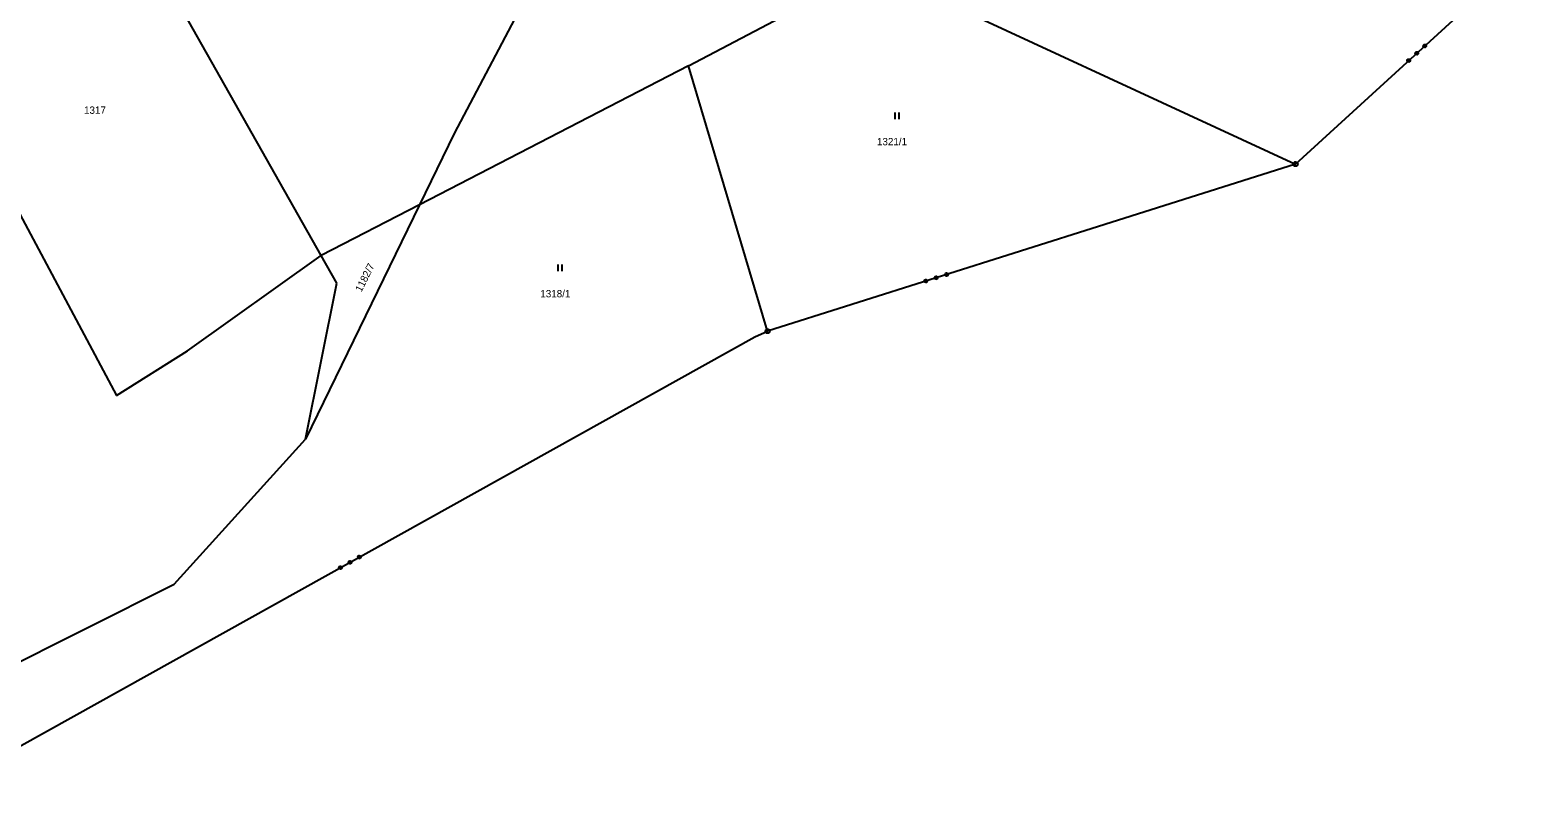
# Model space of a CAD drawing. Extents: x -747792 to -745414, y -1093712 to -1091463.
# Drawn here: x -746991.3 to -746816.9, y -1093671.2 to -1093583.6 of the extents above; entities that cross this region are included whole.
import ezdxf

# ---------------------------------------------------------------- set-up
doc = ezdxf.new("R2010")
doc.units = 0
for name, color, linetype in [('Pracovní_bod JDTM STC_VC', 7, 'Continuous'), ('Pracovní_bod JDTM STC_VC - číslo', 7, 'Continuous'), ('Pracovní_bod NN - výška', 7, 'Continuous'), ('Pracovní_bod VN - výška', 7, 'Continuous')]:
    doc.layers.add(name, color=color, linetype=linetype)

msp = doc.modelspace()

# ---------------------------------------------------------------- linework, layer by layer
at = {"layer": 'Pracovní_bod JDTM STC_VC - číslo'}
for points in [[(-746891.29, -1093593.11), (-746891.29, -1093593.86)], [(-746890.79, -1093593.86), (-746890.79, -1093593.11)], [(-746930.26, -1093610.7), (-746930.26, -1093611.45)], [(-746929.76, -1093611.45), (-746929.76, -1093610.7)]]:
    msp.add_lwpolyline(points, dxfattribs=at)
at = {"layer": 'Pracovní_bod NN - výška'}
for points in [[(-746957.63, -1093609.64), (-746987.25, -1093557.25)], [(-746925, -1093562.76), (-746942.26, -1093595.53)], [(-747010.59, -1093570.96), (-746981.31, -1093625.83)], [(-746844.91, -1093599.07), (-746816.88, -1093573.43)], [(-746915.14, -1093587.71), (-746893.79, -1093576.47)], [(-746893.79, -1093576.47), (-746844.91, -1093599.07)], [(-746830.95, -1093586.08), (-746830.82, -1093586.09), (-746830.73, -1093586.19), (-746830.73, -1093586.32), (-746830.83, -1093586.42), (-746830.97, -1093586.41), (-746831.06, -1093586.31), (-746831.05, -1093586.18), (-746830.95, -1093586.08), (-746830.94, -1093586.1), (-746831.03, -1093586.18), (-746831.03, -1093586.24), (-746830.89, -1093586.11), (-746830.83, -1093586.11), (-746831.04, -1093586.3), (-746831.01, -1093586.33), (-746830.8, -1093586.14), (-746830.77, -1093586.17), (-746830.98, -1093586.36), (-746830.95, -1093586.39), (-746830.75, -1093586.2), (-746830.75, -1093586.25), (-746830.9, -1093586.39), (-746830.84, -1093586.39), (-746830.75, -1093586.31)], [(-746830.03, -1093585.24), (-746829.89, -1093585.24), (-746829.8, -1093585.34), (-746829.81, -1093585.48), (-746829.91, -1093585.57), (-746830.04, -1093585.56), (-746830.13, -1093585.46), (-746830.12, -1093585.33), (-746830.03, -1093585.24), (-746830.03, -1093585.27), (-746830.12, -1093585.35), (-746830.11, -1093585.4), (-746829.97, -1093585.27), (-746829.91, -1093585.27), (-746830.11, -1093585.45), (-746830.08, -1093585.48), (-746829.89, -1093585.3), (-746829.86, -1093585.33), (-746830.05, -1093585.51), (-746830.03, -1093585.54), (-746829.84, -1093585.36), (-746829.82, -1093585.41), (-746829.98, -1093585.54), (-746829.93, -1093585.56), (-746829.84, -1093585.48)], [(-746915.14, -1093587.71), (-746946.28, -1093603.78)], [(-746906, -1093618.4), (-746915.14, -1093587.71)], [(-746831.88, -1093586.93), (-746831.74, -1093586.94), (-746831.65, -1093587.04), (-746831.66, -1093587.17), (-746831.76, -1093587.26), (-746831.89, -1093587.26), (-746831.98, -1093587.16), (-746831.98, -1093587.02), (-746831.88, -1093586.93), (-746831.86, -1093586.94), (-746831.95, -1093587.02), (-746831.95, -1093587.08), (-746831.8, -1093586.95), (-746831.75, -1093586.95), (-746831.95, -1093587.14), (-746831.93, -1093587.17), (-746831.73, -1093586.99), (-746831.7, -1093587.01), (-746831.9, -1093587.19), (-746831.87, -1093587.22), (-746831.67, -1093587.04), (-746831.66, -1093587.09), (-746831.82, -1093587.23), (-746831.77, -1093587.24), (-746831.67, -1093587.15)], [(-746942.26, -1093595.53), (-746946.28, -1093603.78)], [(-746844.91, -1093599.07), (-746866.98, -1093606.05)], [(-746946.28, -1093603.78), (-746959.47, -1093630.89)], [(-746946.28, -1093603.78), (-746957.63, -1093609.64)], [(-746866.98, -1093606.05), (-746906, -1093618.4)], [(-746973.12, -1093620.69), (-746957.63, -1093609.64)], [(-746955.82, -1093612.84), (-746957.63, -1093609.64)], [(-746887.7, -1093612.78), (-746887.82, -1093612.72), (-746887.86, -1093612.59), (-746887.8, -1093612.47), (-746887.67, -1093612.43), (-746887.56, -1093612.49), (-746887.51, -1093612.62), (-746887.58, -1093612.74), (-746887.7, -1093612.78), (-746887.69, -1093612.75), (-746887.58, -1093612.72), (-746887.56, -1093612.67), (-746887.74, -1093612.73), (-746887.79, -1093612.7), (-746887.54, -1093612.62), (-746887.56, -1093612.58), (-746887.8, -1093612.66), (-746887.82, -1093612.62), (-746887.57, -1093612.55), (-746887.58, -1093612.51), (-746887.82, -1093612.58), (-746887.82, -1093612.54), (-746887.62, -1093612.48), (-746887.66, -1093612.45), (-746887.77, -1093612.48)], [(-746886.51, -1093612.4), (-746886.63, -1093612.34), (-746886.67, -1093612.21), (-746886.61, -1093612.09), (-746886.48, -1093612.05), (-746886.36, -1093612.11), (-746886.32, -1093612.24), (-746886.38, -1093612.36), (-746886.51, -1093612.4), (-746886.51, -1093612.38), (-746886.4, -1093612.34), (-746886.37, -1093612.29), (-746886.56, -1093612.35), (-746886.61, -1093612.33), (-746886.34, -1093612.24), (-746886.36, -1093612.2), (-746886.62, -1093612.29), (-746886.63, -1093612.25), (-746886.37, -1093612.17), (-746886.38, -1093612.13), (-746886.65, -1093612.21), (-746886.62, -1093612.16), (-746886.43, -1093612.1), (-746886.48, -1093612.07), (-746886.59, -1093612.11)], [(-746885.31, -1093612.02), (-746885.43, -1093611.96), (-746885.47, -1093611.83), (-746885.41, -1093611.71), (-746885.28, -1093611.67), (-746885.16, -1093611.73), (-746885.12, -1093611.86), (-746885.18, -1093611.98), (-746885.31, -1093612.02), (-746885.32, -1093612), (-746885.21, -1093611.97), (-746885.18, -1093611.92), (-746885.37, -1093611.98), (-746885.41, -1093611.95), (-746885.16, -1093611.87), (-746885.17, -1093611.83), (-746885.42, -1093611.91), (-746885.44, -1093611.87), (-746885.19, -1093611.79), (-746885.2, -1093611.75), (-746885.45, -1093611.83), (-746885.44, -1093611.79), (-746885.23, -1093611.72), (-746885.28, -1093611.69), (-746885.41, -1093611.74)], [(-746959.47, -1093630.89), (-746955.82, -1093612.84)], [(-747001.19, -1093671.22), (-746907.46, -1093619.04)], [(-746907.46, -1093619.04), (-746906, -1093618.4)], [(-746981.31, -1093625.83), (-746973.12, -1093620.69)], [(-746974.65, -1093647.68), (-746959.47, -1093630.89)], [(-746955.44, -1093645.57), (-746955.31, -1093645.6), (-746955.24, -1093645.72), (-746955.28, -1093645.85), (-746955.4, -1093645.92), (-746955.53, -1093645.88), (-746955.59, -1093645.76), (-746955.56, -1093645.63), (-746955.44, -1093645.57), (-746955.42, -1093645.58), (-746955.53, -1093645.64), (-746955.54, -1093645.69), (-746955.37, -1093645.6), (-746955.32, -1093645.62), (-746955.56, -1093645.75), (-746955.54, -1093645.78), (-746955.31, -1093645.65), (-746955.29, -1093645.69), (-746955.52, -1093645.82), (-746955.5, -1093645.85), (-746955.27, -1093645.72), (-746955.27, -1093645.77), (-746955.46, -1093645.87), (-746955.41, -1093645.89), (-746955.28, -1093645.82)], [(-746954.34, -1093644.96), (-746954.21, -1093644.99), (-746954.15, -1093645.11), (-746954.18, -1093645.24), (-746954.3, -1093645.31), (-746954.43, -1093645.27), (-746954.5, -1093645.15), (-746954.46, -1093645.02), (-746954.34, -1093644.96), (-746954.34, -1093644.98), (-746954.44, -1093645.03), (-746954.46, -1093645.09), (-746954.28, -1093644.99), (-746954.23, -1093645.01), (-746954.47, -1093645.14), (-746954.45, -1093645.18), (-746954.21, -1093645.04), (-746954.19, -1093645.08), (-746954.43, -1093645.21), (-746954.41, -1093645.25), (-746954.17, -1093645.11), (-746954.18, -1093645.17), (-746954.36, -1093645.26), (-746954.3, -1093645.28), (-746954.2, -1093645.22)], [(-746953.25, -1093644.35), (-746953.12, -1093644.38), (-746953.05, -1093644.5), (-746953.09, -1093644.63), (-746953.21, -1093644.7), (-746953.33, -1093644.66), (-746953.4, -1093644.54), (-746953.36, -1093644.41), (-746953.25, -1093644.35), (-746953.25, -1093644.37), (-746953.36, -1093644.43), (-746953.36, -1093644.48), (-746953.2, -1093644.39), (-746953.14, -1093644.4), (-746953.37, -1093644.53), (-746953.35, -1093644.57), (-746953.12, -1093644.44), (-746953.11, -1093644.47), (-746953.33, -1093644.6), (-746953.32, -1093644.64), (-746953.09, -1093644.51), (-746953.09, -1093644.56), (-746953.27, -1093644.66), (-746953.23, -1093644.68), (-746953.12, -1093644.62)], [(-747005.6, -1093663.16), (-746974.65, -1093647.68)]]:
    msp.add_lwpolyline(points, dxfattribs=at)
at = {"layer": 'Pracovní_bod VN - výška'}
for points in [[(-746844.83, -1093598.83), (-746844.71, -1093598.93), (-746844.66, -1093599.07), (-746844.71, -1093599.22), (-746844.83, -1093599.31), (-746844.99, -1093599.31), (-746845.11, -1093599.22), (-746845.16, -1093599.07), (-746845.11, -1093598.93), (-746844.99, -1093598.83)], [(-746905.93, -1093618.16), (-746905.8, -1093618.26), (-746905.75, -1093618.4), (-746905.8, -1093618.54), (-746905.93, -1093618.64), (-746906.08, -1093618.64), (-746906.2, -1093618.54), (-746906.25, -1093618.4), (-746906.2, -1093618.26), (-746906.08, -1093618.16)]]:
    msp.add_lwpolyline(points, close=True, dxfattribs=at)
for points in [[(-746844.94, -1093599.07), (-746844.89, -1093599.07)], [(-746906.03, -1093618.4), (-746905.97, -1093618.4)]]:
    msp.add_lwpolyline(points, dxfattribs=at)

# ---------------------------------------------------------------- texts
at = {"layer": 'Pracovní_bod JDTM STC_VC'}
for s, p in [('1317', (-746985.08, -1093593.26)), ('1321/1', (-746893.34, -1093596.9)), ('1318/1', (-746932.29, -1093614.49))]:
    msp.add_text(s, height=0.85, dxfattribs=at).set_placement(p)
msp.add_text('1182/7', height=0.85, rotation=63.541, dxfattribs=at).set_placement((-746952.99, -1093613.94))

doc.saveas('drawing.dxf')
